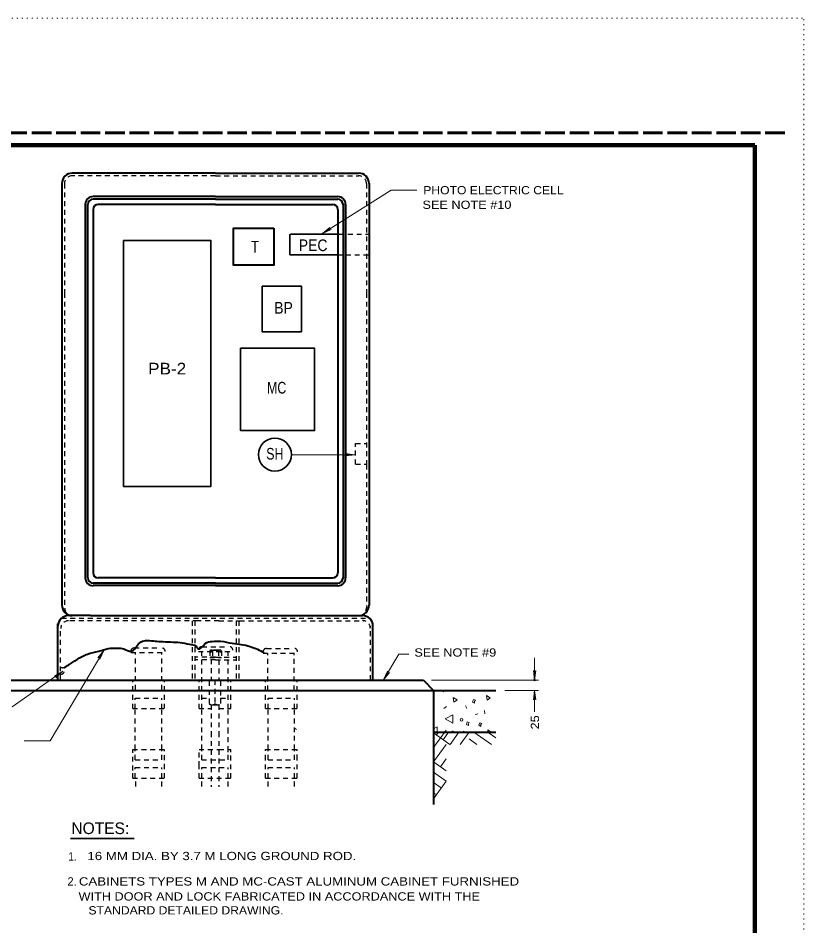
# Model space of a CAD drawing. Extents: x 312583 to 312854, y 144419 to 144597.
# Drawn here: x 312781.2 to 312853.5, y 144513.2 to 144596.8 of the extents above; entities that cross this region are included whole.
import ezdxf
from ezdxf.enums import TextEntityAlignment as Align

# ---------------------------------------------------------------- set-up
doc = ezdxf.new("R2010")
doc.units = 0
doc.header["$LTSCALE"] = 0.3
doc.header["$PDMODE"] = 32
doc.header["$PDSIZE"] = 0.15
for name, pattern in [('DOTTED', [1.5, 0.3, -1.2]), ('LONG_DASHED', [7.5, 6, -1.5]), ('SHORT_DASHED', [2.7, 1.5, -1.2])]:
    doc.linetypes.add(name, pattern=pattern)
for name, color, linetype, lineweight in [('1', 7, 'Continuous', 25), ('2', 7, 'Continuous', 13), ('63', 7, 'DOTTED', 13)]:
    doc.layers.add(name, color=color, linetype=linetype, lineweight=lineweight)

msp = doc.modelspace()

# ---------------------------------------------------------------- linework, layer by layer
at = {"layer": '1', "linetype": 'LONG_DASHED', "lineweight": 60}
msp.add_line((312851.75, 144586.2246), (312583.526, 144586.2246), dxfattribs=at)
at = {"layer": '1', "lineweight": 158}
msp.add_line((312849, 144423.1446), (312849, 144585.0846), dxfattribs=at)
at = {"layer": '1', "lineweight": 40}
for p, q in [((312799.3509, 144582.5173), (312786.1719, 144582.5173)), ((312799.3509, 144582.5173), (312812.5223, 144582.5173)), ((312785.2136, 144581.559), (312785.2136, 144542.7426)), ((312813.4806, 144581.559), (312813.4806, 144542.7426)), ((312799.3509, 144580.363), (312788.0886, 144580.363)), ((312799.3509, 144580.363), (312810.6056, 144580.363)), ((312787.3679, 144579.7343), (312787.3679, 144545.2573)), ((312787.3679, 144579.6423), (312787.3679, 144571.4926)), ((312787.6056, 144545.2573), (312787.6056, 144579.6423)), ((312799.3509, 144580.1176), (312788.0886, 144580.1176)), ((312799.3509, 144579.6423), (312788.5639, 144579.6423)), ((312799.3509, 144580.1176), (312810.6056, 144580.1176)), ((312799.3509, 144579.6423), (312810.1303, 144579.6423)), ((312811.0886, 144579.6423), (312811.0886, 144545.2573)), ((312811.3263, 144579.6423), (312811.3263, 144571.4926)), ((312788.0886, 144579.1593), (312788.0886, 144545.7403)), ((312810.6056, 144579.1593), (312810.6056, 144545.7403)), ((312787.3679, 144571.4926), (312787.3679, 144553.7673)), ((312799.3509, 144545.2573), (312788.5639, 144545.2573)), ((312799.3509, 144545.2573), (312810.1303, 144545.2573)), ((312799.3509, 144544.782), (312788.0886, 144544.782)), ((312799.3509, 144544.5443), (312788.0886, 144544.5443)), ((312799.3509, 144544.782), (312810.6056, 144544.782)), ((312799.3509, 144544.5443), (312810.6056, 144544.5443)), ((312784.8533, 144535.858), (312784.8533, 144541.0406)), ((312787.8509, 144541.7843), (312785.8116, 144541.7843)), ((312787.8509, 144541.7843), (312812.8826, 144541.7843)), ((312813.8409, 144535.858), (312813.8409, 144540.9946)), ((312746.5429, 144535.835), (312818.4946, 144535.835)), ((312799.0366, 144535.858), (312799.5656, 144535.858)), ((312818.4946, 144535.835), (312819.4299, 144534.8996)), ((312745.6076, 144534.8996), (312811.4873, 144534.8996)), ((312779.1799, 144534.8996), (312810.7283, 144534.8996)), ((312810.7283, 144534.8996), (312825.1416, 144534.8996)), ((312819.4299, 144534.8996), (312819.4299, 144524.395)), ((312819.4299, 144531.0663), (312825.1416, 144531.0663))]:
    msp.add_line(p, q, dxfattribs=at)
at = {"layer": '1', "linetype": 'SHORT_DASHED'}
for p, q in [((312799.3509, 144582.2796), (312786.1719, 144582.2796)), ((312799.3509, 144582.2796), (312812.5223, 144582.2796)), ((312785.4513, 144581.559), (312785.4513, 144571.4926)), ((312813.2429, 144581.559), (312813.2429, 144571.4926)), ((312810.7283, 144576.913), (312813.5649, 144576.913)), ((312810.5443, 144574.9963), (312813.5649, 144574.9963)), ((312812.2386, 144557.6313), (312813.2429, 144557.6313)), ((312812.2386, 144555.7146), (312812.2386, 144557.6313)), ((312812.2386, 144555.7146), (312813.2429, 144555.7146)), ((312785.1753, 144541.5466), (312813.5189, 144541.5466)), ((312797.1889, 144541.309), (312797.1889, 144535.858)), ((312797.4343, 144541.309), (312797.4343, 144535.858)), ((312801.2676, 144541.309), (312801.2676, 144535.858)), ((312801.5053, 144541.309), (312801.5053, 144535.858)), ((312785.0909, 144535.858), (312785.0909, 144540.573)), ((312813.6033, 144535.858), (312813.6033, 144540.826)), ((312791.8836, 144538.8096), (312794.2986, 144538.8096)), ((312798.1089, 144538.9246), (312800.5239, 144538.9246)), ((312798.8219, 144538.5336), (312798.8219, 144537.9433)), ((312798.9293, 144538.3573), (312798.9293, 144538.595)), ((312798.9599, 144538.618), (312799.7649, 144538.618)), ((312799.0903, 144538.5336), (312799.0903, 144537.9433)), ((312799.6269, 144538.5336), (312799.6269, 144537.9433)), ((312799.8876, 144538.3573), (312799.8876, 144538.595)), ((312799.8953, 144538.5336), (312799.8953, 144537.9433)), ((312804.0583, 144538.7713), (312806.4733, 144538.7713)), ((312791.5539, 144538.3803), (312794.7279, 144538.3803)), ((312791.9986, 144534.9533), (312791.9986, 144538.3803)), ((312794.4136, 144534.9533), (312794.4136, 144538.3803)), ((312799.3509, 144537.951), (312797.4343, 144537.951)), ((312799.3509, 144537.7133), (312797.4343, 144537.7133)), ((312797.7793, 144538.4953), (312800.9533, 144538.4953)), ((312798.0783, 144533.2283), (312798.0783, 144538.4953)), ((312798.8219, 144537.9433), (312799.8953, 144537.9433)), ((312798.9446, 144537.7593), (312798.9446, 144535.858)), ((312799.3509, 144537.951), (312801.2676, 144537.951)), ((312799.3509, 144537.7133), (312801.2676, 144537.7133)), ((312799.6576, 144537.721), (312799.6576, 144535.858)), ((312800.5239, 144533.2283), (312800.5239, 144538.4953)), ((312803.7286, 144538.342), (312806.9026, 144538.342)), ((312804.1733, 144534.915), (312804.1733, 144538.342)), ((312806.5883, 144534.915), (312806.5883, 144538.342)), ((312791.7303, 144533.2283), (312791.7303, 144535.858)), ((312794.6513, 144533.2283), (312794.6513, 144535.858)), ((312797.8406, 144533.2283), (312797.8406, 144535.858)), ((312798.7759, 144535.766), (312798.7759, 144533.6653)), ((312798.9446, 144535.858), (312799.6576, 144535.858)), ((312799.3049, 144535.858), (312799.3049, 144533.5733)), ((312799.8263, 144535.766), (312799.8263, 144533.6653)), ((312800.7616, 144533.2283), (312800.7616, 144535.858)), ((312803.9509, 144533.2283), (312803.9509, 144535.858)), ((312806.8719, 144533.2283), (312806.8719, 144535.858)), ((312791.9679, 144534.1866), (312794.4136, 144534.1866)), ((312791.9679, 144533.2283), (312791.9679, 144534.1866)), ((312794.4136, 144533.2283), (312794.4136, 144534.1866)), ((312798.0783, 144534.1866), (312798.7759, 144534.1866)), ((312799.0366, 144533.5733), (312799.5656, 144533.5733)), ((312799.8263, 144534.1866), (312800.5239, 144534.1866)), ((312804.1886, 144534.1866), (312806.6343, 144534.1866)), ((312804.1886, 144533.2283), (312804.1886, 144534.1866)), ((312806.6343, 144533.2283), (312806.6343, 144534.1866)), ((312791.7303, 144533.2283), (312794.6513, 144533.2283)), ((312797.8406, 144533.2283), (312798.9446, 144533.2283)), ((312799.6576, 144533.2283), (312800.7616, 144533.2283)), ((312803.9509, 144533.2283), (312806.8719, 144533.2283)), ((312791.7303, 144529.4716), (312794.6513, 144529.4716)), ((312791.9679, 144528.5133), (312791.9679, 144529.4716)), ((312794.4136, 144528.5133), (312794.4136, 144529.4716)), ((312798.0783, 144528.5133), (312798.0783, 144529.4716)), ((312800.5239, 144529.2263), (312800.5239, 144529.4716)), ((312800.7616, 144526.8343), (312800.7616, 144529.4716)), ((312800.7616, 144529.2263), (312800.7616, 144529.4716)), ((312803.9509, 144529.4716), (312806.8719, 144529.4716)), ((312804.1886, 144528.5133), (312804.1886, 144529.4716)), ((312806.6343, 144528.5133), (312806.6343, 144529.4716)), ((312791.9679, 144528.5133), (312794.4136, 144528.5133)), ((312798.0783, 144528.5133), (312798.9446, 144528.5133)), ((312798.9446, 144528.5133), (312800.5239, 144528.5133)), ((312804.1886, 144528.5133), (312806.6343, 144528.5133)), ((312791.9679, 144527.7926), (312794.4136, 144527.7926)), ((312791.9679, 144526.8343), (312791.9679, 144527.7926)), ((312794.4136, 144526.8343), (312794.4136, 144527.7926)), ((312798.0783, 144526.8343), (312798.0783, 144527.7926)), ((312798.0783, 144527.7926), (312800.5239, 144527.7926)), ((312800.5239, 144526.8343), (312800.5239, 144527.7926)), ((312804.1886, 144527.7926), (312806.6343, 144527.7926)), ((312804.1886, 144526.8343), (312804.1886, 144527.7926)), ((312806.6343, 144526.8343), (312806.6343, 144527.7926)), ((312791.7303, 144526.8343), (312794.6513, 144526.8343)), ((312792.0216, 144526.06), (312792.0216, 144526.8343)), ((312794.4136, 144526.06), (312794.4136, 144526.8343)), ((312797.8406, 144526.8343), (312800.7616, 144526.8343)), ((312798.0783, 144526.06), (312798.0783, 144526.8343)), ((312800.5239, 144526.06), (312800.5239, 144526.8343)), ((312803.9509, 144526.8343), (312806.8719, 144526.8343)), ((312804.1886, 144526.06), (312804.1886, 144526.8343)), ((312806.6343, 144526.06), (312806.6343, 144526.8343))]:
    msp.add_line(p, q, dxfattribs=at)
at = {"layer": '1', "lineweight": 35}
for p, q in [((312806.1896, 144574.9963), (312806.1896, 144576.913)), ((312806.2586, 144576.913), (312810.7283, 144576.913)), ((312806.1896, 144574.9963), (312810.5443, 144574.9963))]:
    msp.add_line(p, q, dxfattribs=at)
at = {"layer": '1', "lineweight": 13}
msp.add_line((312799.8263, 144534.4473), (312799.8493, 144534.4396), dxfattribs=at)
at = {"layer": '1', "lineweight": 158}
msp.add_lwpolyline([(312616.5, 144423.1446), (312616.5, 144585.0846), (312849, 144585.0846)], dxfattribs=at)
at = {"layer": '1', "lineweight": 40}
msp.add_lwpolyline([(312804.7329, 144577.465), (312804.7329, 144574.0456), (312801.0146, 144574.0456), (312801.0146, 144577.465)], close=True, dxfattribs=at)
at = {"layer": '1', "lineweight": 35}
for points in [[(312790.8793, 144576.3226), (312790.8793, 144553.6753), (312798.9369, 144553.6753), (312798.9369, 144576.3226)], [(312803.6443, 144572.1136), (312803.6443, 144567.9123), (312807.2553, 144567.9123), (312807.2553, 144572.1136)], [(312801.6586, 144566.402), (312801.6586, 144558.812), (312808.4666, 144558.812), (312808.4666, 144566.402)]]:
    msp.add_lwpolyline(points, close=True, dxfattribs=at)
at = {"layer": '1', "linetype": 'SHORT_DASHED'}
for points in [[(312785.4513, 144571.4926), (312785.4513, 144553.7673), (312785.4513, 144542.4666)], [(312813.2429, 144571.4926), (312813.2429, 144555.684), (312813.2429, 144542.505)], [(312799.6653, 144541.309), (312797.7486, 144541.309), (312785.8193, 144541.309)], [(312799.6653, 144541.309), (312801.5819, 144541.309), (312812.9669, 144541.309)], [(312798.9906, 144538.618), (312799.2896, 144538.618), (312799.2359, 144538.6026), (312799.2053, 144538.595), (312799.1516, 144538.5796), (312799.0903, 144538.5413), (312799.0749, 144538.572), (312799.0443, 144538.5873), (312799.0059, 144538.6103), (312799.2666, 144538.6103), (312799.1899, 144538.595), (312799.1363, 144538.572), (312799.0979, 144538.549), (312799.0519, 144538.5873), (312799.0213, 144538.6103), (312799.2359, 144538.6103), (312799.1593, 144538.5873), (312799.0979, 144538.5566), (312799.0366, 144538.6026), (312799.2129, 144538.6103), (312799.0903, 144538.5566), (312799.0443, 144538.6026), (312799.1899, 144538.6026), (312799.0903, 144538.5643), (312799.0596, 144538.6026), (312799.1669, 144538.6026), (312799.0903, 144538.572), (312799.0673, 144538.595), (312799.1363, 144538.595), (312799.0979, 144538.5796), (312799.0826, 144538.595), (312799.1133, 144538.5873), (312799.0979, 144538.5873)], [(312799.7266, 144538.618), (312799.4276, 144538.618), (312799.4813, 144538.6026), (312799.5119, 144538.595), (312799.5656, 144538.5796), (312799.6269, 144538.5413), (312799.6423, 144538.572), (312799.6729, 144538.5873), (312799.7189, 144538.6103), (312799.4506, 144538.6103), (312799.5273, 144538.595), (312799.5809, 144538.572), (312799.6193, 144538.549), (312799.6653, 144538.5873), (312799.6959, 144538.6103), (312799.4813, 144538.6103), (312799.5579, 144538.5873), (312799.6193, 144538.5566), (312799.6806, 144538.6026), (312799.5119, 144538.6103), (312799.6269, 144538.5566), (312799.6729, 144538.6026), (312799.5273, 144538.6026), (312799.6269, 144538.5643), (312799.6576, 144538.6026), (312799.5503, 144538.6026), (312799.6269, 144538.572), (312799.6499, 144538.595), (312799.5809, 144538.595), (312799.6193, 144538.5796), (312799.6346, 144538.595), (312799.6039, 144538.5873), (312799.6269, 144538.5873)], [(312799.1133, 144535.858), (312799.4966, 144535.858), (312799.4506, 144535.8503), (312799.4123, 144535.835), (312799.3663, 144535.8196), (312799.3433, 144535.8043), (312799.3049, 144535.7813), (312799.3049, 144535.7736), (312799.2283, 144535.8196), (312799.1669, 144535.8426), (312799.1286, 144535.858), (312799.4736, 144535.858), (312799.4429, 144535.8503), (312799.4123, 144535.8426), (312799.3663, 144535.8273), (312799.3279, 144535.8043), (312799.3126, 144535.7966), (312799.2973, 144535.7813), (312799.2359, 144535.8273), (312799.1669, 144535.8503), (312799.4199, 144535.8503), (312799.3586, 144535.8273), (312799.3049, 144535.7966), (312799.1899, 144535.8503), (312799.3969, 144535.8503), (312799.3049, 144535.789), (312799.2129, 144535.8426), (312799.3739, 144535.8426), (312799.3049, 144535.8043), (312799.2436, 144535.835), (312799.3509, 144535.835), (312799.3049, 144535.8196), (312799.2436, 144535.835), (312799.2819, 144535.812), (312799.2896, 144535.835), (312799.2973, 144535.7966), (312799.3203, 144535.8273), (312799.3356, 144535.8273), (312799.3586, 144535.835)], [(312798.9446, 144533.5733), (312798.9446, 144531.051), (312798.9446, 144526.014)], [(312799.1133, 144533.5733), (312799.4966, 144533.5733), (312799.4506, 144533.581), (312799.4123, 144533.5963), (312799.3663, 144533.6116), (312799.3433, 144533.627), (312799.3049, 144533.6576), (312799.3049, 144533.6576), (312799.2283, 144533.6116), (312799.1669, 144533.5886), (312799.1286, 144533.581), (312799.4736, 144533.5733), (312799.4429, 144533.581), (312799.4123, 144533.5886), (312799.3663, 144533.604), (312799.3279, 144533.627), (312799.3126, 144533.6346), (312799.2973, 144533.65), (312799.2359, 144533.6116), (312799.1669, 144533.581), (312799.4199, 144533.581), (312799.3586, 144533.604), (312799.3049, 144533.6346), (312799.1899, 144533.5886), (312799.3969, 144533.581), (312799.3049, 144533.6423), (312799.2129, 144533.5886), (312799.3739, 144533.5886), (312799.3049, 144533.627), (312799.2436, 144533.5963), (312799.3509, 144533.5963), (312799.3049, 144533.6116), (312799.2436, 144533.604), (312799.2819, 144533.6193), (312799.2896, 144533.5963), (312799.2973, 144533.6346), (312799.3203, 144533.604), (312799.3356, 144533.604), (312799.3586, 144533.5963)], [(312799.6576, 144533.5733), (312799.6576, 144531.051), (312799.6576, 144526.0293)], [(312791.9679, 144529.4716), (312791.9679, 144531.051), (312791.9679, 144533.2283)], [(312794.4136, 144529.4716), (312794.4136, 144531.051), (312794.4136, 144533.2283)], [(312798.0783, 144529.4716), (312798.0783, 144531.051), (312798.0783, 144533.2283)], [(312800.5239, 144528.5133), (312800.5239, 144531.051), (312800.5239, 144533.2283)], [(312804.1886, 144529.4716), (312804.1886, 144531.051), (312804.1886, 144533.2283)], [(312806.6343, 144529.4716), (312806.6343, 144531.051), (312806.6343, 144533.2283)], [(312791.7303, 144526.8343), (312791.7303, 144527.5396), (312791.7303, 144529.4716)], [(312794.6513, 144526.8343), (312794.6513, 144527.6853), (312794.6513, 144529.4716)], [(312797.8406, 144529.4716), (312799.6576, 144529.4716), (312800.7616, 144529.4716)], [(312797.8406, 144526.8343), (312797.8406, 144527.9306), (312797.8406, 144529.4716)], [(312803.9509, 144526.8343), (312803.9509, 144528.5286), (312803.9509, 144529.4716)], [(312806.8719, 144526.8343), (312806.8719, 144528.544), (312806.8719, 144529.4716)]]:
    msp.add_lwpolyline(points, dxfattribs=at)
at = {"layer": '1', "lineweight": 40}
msp.add_lwpolyline([(312811.3263, 144571.4926), (312811.3263, 144553.7673), (312811.3263, 144545.2573)], dxfattribs=at)
for centre, radius, start, end in [((312786.171, 144581.558), 0.9583, 90, 180), ((312812.5251, 144581.558), 0.9583, 0, 90), ((312788.0876, 144579.6413), 0.7188, 90, 180), ((312810.6085, 144579.6413), 0.7188, 0, 90), ((312788.0876, 144579.6413), 0.4792, 90, 180), ((312788.5668, 144579.1622), 0.4792, 90, 180), ((312810.1293, 144579.1622), 0.4792, 0, 90), ((312810.6085, 144579.6413), 0.4792, 0, 90), ((312788.0876, 144545.2611), 0.7188, 180, 270), ((312788.0876, 144545.2611), 0.4792, 180, 270), ((312788.5668, 144545.7403), 0.4792, 180, 270), ((312810.1293, 144545.7403), 0.4792, 270, 0), ((312810.6085, 144545.2611), 0.7188, 270, 0), ((312810.6085, 144545.2611), 0.4792, 270, 0), ((312786.171, 144542.7455), 0.9583, 180, 270), ((312812.5251, 144542.7455), 0.9583, 270, 0), ((312785.8116, 144540.8288), 0.9583, 90, 180), ((312812.8845, 144540.8288), 0.9583, 0, 90)]:
    msp.add_arc(centre, radius, start, end, dxfattribs=at)
at = {"layer": '1', "linetype": 'SHORT_DASHED'}
for centre, radius, start, end in [((312786.171, 144581.558), 0.7188, 90, 180), ((312812.5251, 144581.558), 0.7188, 0, 90), ((312786.1911, 144542.4647), 0.7188, 180, 233.89913), ((312812.5251, 144542.5059), 0.7188, 270, 0), ((312785.8212, 144540.5893), 0.7188, 90, 180), ((312812.8845, 144540.6094), 0.7188, 0, 90), ((312791.8841, 144538.466), 0.3437, 90.411, 194.26621), ((312794.3833, 144538.4765), 0.3437, 0.411, 104.26621), ((312798.1085, 144538.5838), 0.3437, 90.411, 194.26621), ((312798.9556, 144538.4695), 0.1489, 25.60064, 154.39936), ((312799.3586, 144538.1496), 0.4689, 55.04559, 124.95441), ((312799.7616, 144538.4695), 0.1489, 25.60064, 154.39936), ((312800.6077, 144538.5944), 0.3437, 0.411, 104.26621), ((312804.0607, 144538.4276), 0.3437, 90.411, 194.26621), ((312806.5599, 144538.4382), 0.3437, 0.411, 104.26621), ((312799.0389, 144535.4536), 0.4079, 50.00693, 129.99306), ((312799.5632, 144535.4536), 0.4079, 50.00694, 129.99307), ((312799.0389, 144533.9797), 0.4079, 230.00694, 309.99307), ((312799.5632, 144533.9797), 0.4079, 230.00693, 309.99306)]:
    msp.add_arc(centre, radius, start, end, dxfattribs=at)
at = {"layer": '1', "lineweight": 40}
msp.add_spline([(312785.3593, 144536.9773), (312785.8499, 144537.261), (312786.6089, 144537.7516), (312787.5673, 144538.2423), (312788.6099, 144538.5106), (312789.4839, 144538.756), (312790.2889, 144538.802), (312790.9099, 144538.7176), (312791.5769, 144538.5106), (312792.3819, 144539.2926), (312792.9186, 144539.492), (312793.6316, 144539.4536), (312794.2986, 144539.4076), (312795.2186, 144539.3616), (312796.0849, 144539.3156), (312796.9513, 144539.1623), (312797.5569, 144538.963), (312797.7793, 144538.7176), (312798.4079, 144539.2083), (312799.0519, 144539.4076), (312799.8569, 144539.4306), (312800.8766, 144539.2466), (312801.7276, 144539.1393), (312802.5326, 144538.94), (312803.2226, 144538.6946), (312803.8053, 144538.3573)], degree=3, dxfattribs=at)
at = {"layer": '2'}
for p, q in [((312815.5276, 144580.9456), (312809.2103, 144576.9666)), ((312815.5276, 144580.9456), (312817.8889, 144580.9456)), ((312809.2103, 144576.9666), (312809.8849, 144577.5186)), ((312809.2103, 144576.9666), (312809.9999, 144577.3346)), ((312809.8849, 144577.5186), (312809.7086, 144577.281)), ((312809.9999, 144577.3346), (312809.7086, 144577.281)), ((312806.3353, 144556.5963), (312812.1696, 144556.5963)), ((312811.3033, 144556.7036), (312811.5793, 144556.5963)), ((312812.1696, 144556.5963), (312811.3033, 144556.7036)), ((312811.3033, 144556.489), (312811.5793, 144556.5963)), ((312812.1696, 144556.5963), (312811.3033, 144556.489)), ((312784.1249, 144530.269), (312789.0623, 144538.5796)), ((312789.0623, 144538.5796), (312788.5333, 144537.8896)), ((312789.0623, 144538.5796), (312788.7173, 144537.7823)), ((312788.5333, 144537.8896), (312788.7633, 144538.0736)), ((312788.7173, 144537.7823), (312788.7633, 144538.0736)), ((312816.2253, 144538.2423), (312814.8146, 144535.8656)), ((312816.2253, 144538.2423), (312817.1529, 144538.2423)), ((312828.7143, 144535.858), (312828.7143, 144537.905)), ((312780.6443, 144533.397), (312785.2979, 144536.663)), ((312785.2979, 144536.663), (312784.5236, 144536.249)), ((312784.5236, 144536.249), (312784.8149, 144536.3256)), ((312785.2979, 144536.663), (312784.6463, 144536.0803)), ((312784.6463, 144536.0803), (312784.8149, 144536.3256)), ((312814.8146, 144535.8656), (312815.1673, 144536.6706)), ((312814.8146, 144535.8656), (312815.3513, 144536.5556)), ((312815.1673, 144536.6706), (312815.1213, 144536.3793)), ((312815.3513, 144536.5556), (312815.1213, 144536.3793)), ((312828.6069, 144536.7243), (312828.7143, 144536.4483)), ((312828.7143, 144535.858), (312828.6069, 144536.7243)), ((312828.8216, 144536.7243), (312828.7143, 144536.4483)), ((312828.7143, 144535.858), (312828.8216, 144536.7243)), ((312819.2459, 144535.858), (312829.0746, 144535.858)), ((312819.4299, 144534.5393), (312819.4759, 144534.524)), ((312825.9696, 144534.8996), (312829.0746, 144534.8996)), ((312828.7143, 144534.8996), (312828.6069, 144534.0333)), ((312828.7143, 144534.8996), (312828.8216, 144534.0333)), ((312828.7143, 144532.937), (312828.7143, 144534.8996)), ((312794.6513, 144534.2403), (312794.6589, 144534.2556)), ((312828.6069, 144534.0333), (312828.7143, 144534.3093)), ((312828.8216, 144534.0333), (312828.7143, 144534.3093)), ((312820.6259, 144533.4276), (312820.3576, 144533.2283)), ((312822.3509, 144533.489), (312822.4889, 144533.236)), ((312823.2633, 144532.6993), (312823.4856, 144532.7606)), ((312824.1066, 144533.052), (312824.1449, 144532.7376)), ((312806.8029, 144531.3116), (312806.6343, 144531.4113)), ((312820.5723, 144531.235), (312819.4299, 144529.6326)), ((312819.8669, 144531.051), (312819.6906, 144530.798)), ((312820.8099, 144531.051), (312820.3116, 144530.3533)), ((312821.7529, 144531.051), (312820.9403, 144529.9086)), ((312821.0476, 144531.0663), (312821.2239, 144531.166)), ((312822.6959, 144531.051), (312821.8756, 144529.9086)), ((312824.7429, 144529.924), (312823.1406, 144531.0663)), ((312825.1416, 144530.5373), (312824.4439, 144531.0356)), ((312781.7329, 144530.269), (312784.1249, 144530.269)), ((312820.9096, 144529.924), (312819.4299, 144530.982)), ((312823.4166, 144529.924), (312822.6959, 144530.4453)), ((312791.9679, 144529.5253), (312791.8683, 144529.4716)), ((312820.5723, 144529.9163), (312819.4299, 144528.314)), ((312820.5723, 144528.59), (312820.0509, 144527.8616)), ((312819.4299, 144528.314), (312820.5723, 144527.4936)), ((312819.4299, 144527.371), (312820.5723, 144526.5583)), ((312820.5723, 144526.5583), (312819.4069, 144524.9253)), ((312819.4299, 144526.428), (312820.1276, 144525.9296)), ((312819.4299, 144525.485), (312819.6829, 144525.3086))]:
    msp.add_line(p, q, dxfattribs=at)
at = {"layer": '2', "lineweight": 35}
msp.add_line((312786.0168, 144521.2595), (312791.8588, 144521.2595), dxfattribs=at)
at = {"layer": '2'}
for points in [[(312796.4299, 144535.858), (312796.4299, 144535.8196), (312796.5219, 144535.858)], [(312820.1659, 144534.8996), (312820.1506, 144534.869), (312820.3423, 144534.7616), (312820.3423, 144534.8996)], [(312819.7673, 144531.0663), (312819.7673, 144531.5416), (312819.4299, 144531.373)], [(312822.3203, 144531.074), (312822.1899, 144531.1506), (312822.1976, 144531.0663)], [(312824.7276, 144531.0663), (312824.4056, 144531.2656), (312824.4286, 144531.074)]]:
    msp.add_lwpolyline(points, dxfattribs=at)
for points in [[(312824.3519, 144534.018), (312824.6433, 144534.2326), (312824.2906, 144534.4473)], [(312821.3006, 144533.8263), (312821.5919, 144534.041), (312821.2393, 144534.2556)], [(312823.2019, 144533.8876), (312823.2709, 144534.0026), (312823.1023, 144534.0563), (312823.0103, 144533.834), (312823.2019, 144533.7266)], [(312821.1856, 144531.879), (312821.1856, 144532.6456), (312820.4879, 144532.3006)], [(312822.6346, 144531.8253), (312822.7036, 144531.948), (312822.5273, 144532.0016), (312822.4429, 144531.7716), (312822.6346, 144531.6643)], [(312823.7846, 144531.7486), (312823.8536, 144531.8713), (312823.6773, 144531.9173), (312823.5853, 144531.695), (312823.7846, 144531.5876)]]:
    msp.add_lwpolyline(points, close=True, dxfattribs=at)
at = {"layer": '2', "lineweight": 35}
msp.add_circle((312804.8187, 144556.6054), 1.52, dxfattribs=at)
at = {"layer": '2'}
msp.add_circle((312821.9847, 144532.1919), 0.1298, dxfattribs=at)
at = {"layer": '2', "linetype": 'SHORT_DASHED', "lineweight": 25}
msp.add_arc((312785.1178, 144536.6917), 0.3097, 264.63342, 94.61635, dxfattribs=at)
at = {"layer": '2'}
msp.add_point((312828.7143, 144535.858), dxfattribs=at)
at = {"layer": '63'}
msp.add_line((312601.2, 144596.7846), (312853.5, 144596.7846), dxfattribs=at)
msp.add_lwpolyline([(312601.2, 144418.5846), (312853.5, 144418.5846), (312853.5, 144596.7846)], dxfattribs=at)

# ---------------------------------------------------------------- texts
at = {"layer": '2'}
for s, width, p in [('PHOTO ELECTRIC CELL', 1.1, (312818.4716, 144580.5694)), ('SEE NOTE #10', 1.15, (312818.4016, 144579.2278)), ('SEE NOTE #9', 1.15, (312817.6534, 144538.013)), ('1.', 0.9, (312785.8104, 144519.2335)), ('16 MM DIA. BY 3.7 M LONG GROUND ROD.', 1.2, (312787.564, 144519.2795)), ('  CABINETS TYPES M AND MC-CAST ALUMINUM CABINET FURNISHED   ', 1.2, (312786.097, 144516.9405)), ('  WITH DOOR AND LOCK FABRICATED IN ACCORDANCE WITH THE', 1.15, (312786.097, 144515.5605)), ('STANDARD DETAILED DRAWING.  ', 1.1, (312787.6582, 144514.2781))]:
    msp.add_text(s, height=0.76, dxfattribs=dict(at, width=width)).set_placement(p)
for s, width, p in [('T', 0.8, (312802.9887, 144575.211)), ('PEC', 0.9, (312808.3362, 144575.3413)), ('BP', 0.9, (312805.6145, 144569.5836)), ('PB-2', 1.1, (312794.9004, 144563.987)), ('MC', 0.8, (312804.9782, 144562.2313)), ('SH', 0.8, (312804.8134, 144556.1516))]:
    msp.add_text(s, height=1.072, dxfattribs=dict(at, width=width)).set_placement(p, align=Align.CENTER)
at = {"layer": '2', "width": 1.15}
msp.add_text('25 ', height=0.76, rotation=90, dxfattribs=at).set_placement((312829.1297, 144531.3103))
at = {"layer": '2'}
msp.add_text('NOTES:', height=1.07, dxfattribs=at).set_placement((312788.7508, 144521.6781), align=Align.CENTER)
msp.add_text('2.', height=0.76, dxfattribs=at).set_placement((312785.7268, 144516.9405))

doc.saveas('drawing.dxf')
